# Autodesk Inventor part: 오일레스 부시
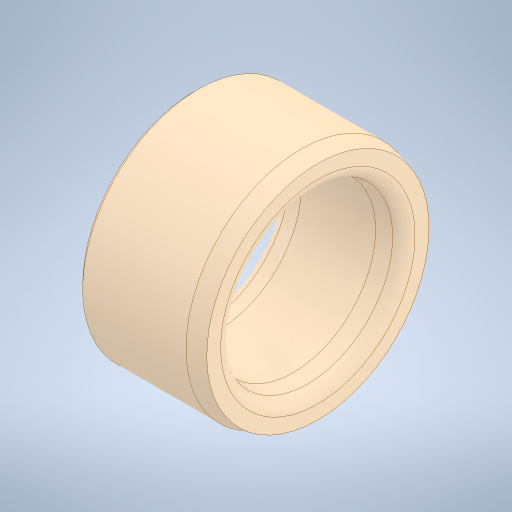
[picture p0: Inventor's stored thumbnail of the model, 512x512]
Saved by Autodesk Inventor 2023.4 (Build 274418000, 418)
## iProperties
Created: 2024-05
Part Number: 오일레스 부시
Material: 구리, 합금
Document SubType Name: Modeling
Designer: user
Density: 8.92 g/cm^3
Appearance: 기본값
Author: jhkim
Sending System: Autodesk Inventor 2025
Preprocessor: ST-DEVELOPER v20
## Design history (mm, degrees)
feature "솔리드1"
node "솔리드2"
